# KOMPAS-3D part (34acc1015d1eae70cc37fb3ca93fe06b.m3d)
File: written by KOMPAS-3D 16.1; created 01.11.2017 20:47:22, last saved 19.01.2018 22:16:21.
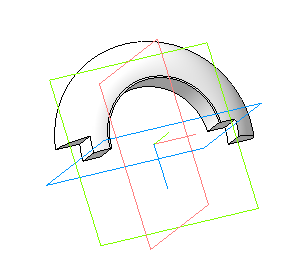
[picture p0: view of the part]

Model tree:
1. Эскиз:1
2. Операция выдавливания:1
     Расстояние 1 = 10
3. Эскиз:2
4. Вырезать элемент вращения:2
     Угол 1 = 360
5. Эскиз:4
6. Вырезать элемент выдавливания:2
     Расстояние 1 = 10

Expressions: v170/2
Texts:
  Строгонов Владимир Леонидович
